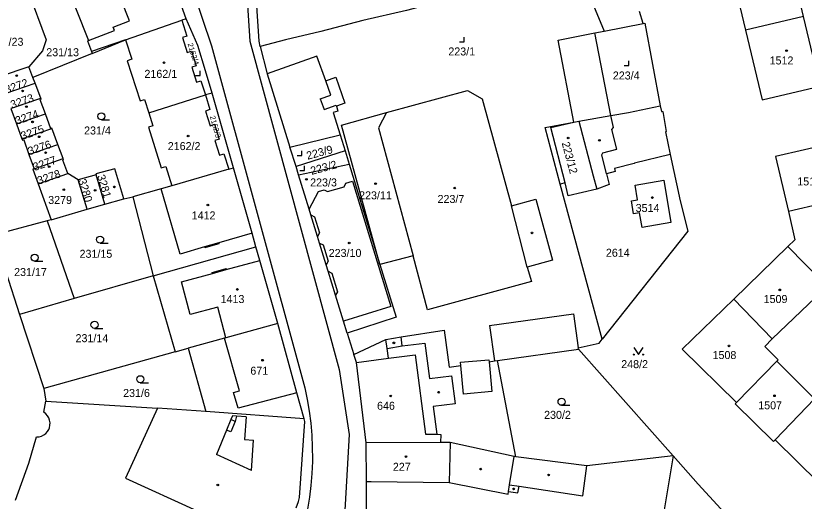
# Model space of a CAD drawing. Extents: x -679220 to -673243, y -1075091 to -1066557.
# Drawn here: x -676182 to -676014.5, y -1071736.7 to -1071633.5 of the extents above; entities that cross this region are included whole.
import ezdxf

# ---------------------------------------------------------------- set-up
doc = ezdxf.new("R2010")
doc.units = 0
for name, color, linetype in [('Hranice parcel', 7, 'Continuous'), ('Parcelní čísla', 7, 'Continuous'), ('Vnitřní kresba', 7, 'Continuous'), ('Značky budov', 7, 'Continuous'), ('Značky kultur', 7, 'Continuous')]:
    doc.layers.add(name, color=color, linetype=linetype)

msp = doc.modelspace()

# ---------------------------------------------------------------- linework, layer by layer
at = {"layer": 'Hranice parcel'}
for p, q in [((-676145.76, -1071634.12), (-676151.72, -1071617.55)), ((-676048.69, -1071635.13), (-676049.48, -1071632.57)), ((-676158.64, -1071638.61), (-676146.7, -1071634.45)), ((-676145.76, -1071634.12), (-676146.7, -1071634.45)), ((-676014.66, -1071633.66), (-676026.99, -1071636.54)), ((-676165.71, -1071641.49), (-676158.64, -1071638.61)), ((-676165.71, -1071641.49), (-676178.31, -1071646.61)), ((-676179.16, -1071644.33), (-676185.27, -1071646.43)), ((-676178.31, -1071646.61), (-676179.16, -1071644.33)), ((-676184, -1071649.93), (-676177.86, -1071647.82)), ((-676177.86, -1071647.82), (-676178.31, -1071646.61)), ((-676176.67, -1071651.01), (-676177.86, -1071647.82)), ((-676182.84, -1071653.13), (-676176.67, -1071651.01)), ((-676153.73, -1071654.12), (-676141.7, -1071650.33)), ((-676140.29, -1071649.98), (-676141.7, -1071650.33)), ((-676135.76, -1071665.81), (-676140.29, -1071649.98)), ((-676181.78, -1071656.49), (-676175.68, -1071654.37)), ((-676174.53, -1071657.5), (-676175.68, -1071654.37)), ((-676112.77, -1071656.77), (-676103.2, -1071654.04)), ((-676181.78, -1071656.49), (-676180.65, -1071659.66)), ((-676180.65, -1071659.66), (-676174.53, -1071657.5)), ((-676179.17, -1071662.97), (-676173.03, -1071660.83)), ((-676171.92, -1071663.86), (-676173.03, -1071660.83)), ((-676179.17, -1071662.97), (-676178.07, -1071666.01)), ((-676122.44, -1071665.53), (-676123.73, -1071661.42)), ((-676112.02, -1071662.17), (-676122.44, -1071665.53)), ((-676112.02, -1071662.17), (-676111.15, -1071665.03)), ((-676178.07, -1071666.01), (-676171.92, -1071663.86)), ((-676136.74, -1071666.1), (-676148.81, -1071669.62)), ((-676136.74, -1071666.1), (-676135.76, -1071665.81)), ((-676121.9, -1071667.28), (-676122.44, -1071665.53)), ((-676121.9, -1071667.28), (-676111.15, -1071665.03)), ((-676177.24, -1071669.21), (-676170.92, -1071667.01)), ((-676168.68, -1071668.36), (-676170.92, -1071667.01)), ((-676164.91, -1071667.31), (-676168.68, -1071668.36)), ((-676163.04, -1071673.55), (-676164.91, -1071667.31)), ((-676119.65, -1071674.63), (-676121.9, -1071667.28)), ((-676177.24, -1071669.21), (-676174.48, -1071676.86)), ((-676166.79, -1071674.64), (-676168.68, -1071668.36)), ((-676057.44, -1071702.25), (-676066.33, -1071669.3)), ((-676163.04, -1071673.55), (-676159.05, -1071672.4)), ((-676159.05, -1071672.4), (-676157.09, -1071671.95)), ((-676157.09, -1071671.95), (-676152.82, -1071688.75)), ((-676005.59, -1071672.24), (-676017.88, -1071675.12)), ((-676174.48, -1071676.86), (-676166.79, -1071674.64)), ((-676166.79, -1071674.64), (-676163.04, -1071673.55)), ((-676175.28, -1071677.08), (-676186.72, -1071680.18)), ((-676174.48, -1071676.86), (-676175.28, -1071677.08)), ((-676175.28, -1071677.08), (-676169.53, -1071693.6)), ((-676152.82, -1071688.75), (-676130.95, -1071682.6)), ((-676017.97, -1071682.56), (-676029.47, -1071693.75)), ((-676009.72, -1071691.04), (-676017.97, -1071682.56)), ((-676152.82, -1071688.75), (-676169.53, -1071693.6)), ((-676152.82, -1071688.75), (-676148.14, -1071704.96)), ((-676021.31, -1071702.14), (-676009.72, -1071691.04)), ((-676169.53, -1071693.6), (-676181.15, -1071696.97)), ((-676021.31, -1071702.14), (-676029.47, -1071693.75)), ((-676181.15, -1071696.97), (-676176.04, -1071712.7)), ((-676111.57, -1071700.93), (-676112.37, -1071698.39)), ((-676111.57, -1071700.93), (-676110.14, -1071705.5)), ((-676148.14, -1071704.96), (-676145.33, -1071704.18)), ((-676145.33, -1071704.18), (-676141.6, -1071717.61)), ((-676079.69, -1071706.8), (-676062.48, -1071704.34)), ((-676062.48, -1071704.34), (-676042.38, -1071727.03)), ((-676148.14, -1071704.96), (-676176.04, -1071712.7)), ((-676075.79, -1071727.22), (-676079.69, -1071706.8)), ((-676020.31, -1071706.89), (-676028.93, -1071715.7)), ((-676012.33, -1071714.92), (-676020.31, -1071706.89)), ((-676176.04, -1071712.7), (-676175.61, -1071715.39)), ((-676012.33, -1071714.92), (-676020.69, -1071723.63)), ((-676175.98, -1071717.78), (-676175.61, -1071715.39)), ((-676175.61, -1071715.39), (-676151.9, -1071716.94)), ((-676141.6, -1071717.61), (-676151.9, -1071716.94)), ((-676120.74, -1071719.2), (-676141.6, -1071717.61)), ((-676042.38, -1071727.03), (-676048.46, -1071763.85))]:
    msp.add_line(p, q, dxfattribs=at)
for points in [[(-676099.38, -1071590.43), (-676125.1, -1071603.36), (-676134.03, -1071611.63), (-676132.28, -1071638.9), (-676113.31, -1071708.7), (-676111.17, -1071722.51), (-676112.16, -1071739.84), (-676114.63, -1071749.43), (-676121.41, -1071764.03), (-676135.15, -1071783.33), (-676142.46, -1071792.76), (-676166.36, -1071822.04), (-676175.39, -1071833.12), (-676182.45, -1071844.4), (-676187.2, -1071855.01), (-676191.45, -1071871.27), (-676192.51, -1071884.43), (-676191.2, -1071899.37), (-676183.88, -1071917.06), (-676171.89, -1071936.65), (-676157.14, -1071950.29), (-676143.77, -1071959.8), (-676108.24, -1071982.64), (-676103.47, -1071979.82)], [(-676130.08, -1071640.05), (-676130.27, -1071638.92), (-676132.05, -1071612.1), (-676123.87, -1071605), (-676098.3, -1071593.66)], [(-676152.11, -1071615.93), (-676148.36, -1071616.28), (-676140.37, -1071639.9), (-676120.56, -1071712.56)], [(-676014.66, -1071633.66), (-676018.16, -1071618.83), (-676030.51, -1071621.69), (-676026.99, -1071636.54)], [(-676171.89, -1071625.11), (-676166.49, -1071638.73), (-676166.73, -1071638.83), (-676165.85, -1071641.12), (-676165.71, -1071641.49)], [(-676084.03, -1071625.87), (-676089.49, -1071628.58), (-676093.25, -1071630.57), (-676095.5, -1071631.44), (-676098.98, -1071632.38), (-676108.29, -1071634.5), (-676117.2, -1071636.81), (-676124.66, -1071638.59), (-676130.08, -1071640.05)], [(-676179.39, -1071628.06), (-676175.53, -1071638.64), (-676176.27, -1071640.96), (-676179.16, -1071644.33)], [(-676146.7, -1071634.45), (-676145.64, -1071637.82), (-676146.59, -1071638.12), (-676145.6, -1071641.29), (-676144.64, -1071640.99), (-676143.65, -1071644.15), (-676144.6, -1071644.45), (-676143.6, -1071647.63), (-676142.65, -1071647.33), (-676141.7, -1071650.33)], [(-676140.29, -1071649.98), (-676141.65, -1071645.22), (-676143.3, -1071639.79), (-676145.76, -1071634.12)], [(-676026.99, -1071636.54), (-676023.47, -1071651.39), (-676011.16, -1071648.49), (-676014.66, -1071633.66)], [(-676063.46, -1071656.11), (-676066.78, -1071638.69), (-676058.99, -1071637.15), (-676057.03, -1071636.77), (-676048.69, -1071635.13)], [(-676048.69, -1071635.13), (-676048.4, -1071635.08), (-676045.08, -1071652.62)], [(-676158.64, -1071638.61), (-676157.33, -1071642.74), (-676158.28, -1071643.05), (-676155.58, -1071651.59), (-676154.62, -1071651.29), (-676153.73, -1071654.12)], [(-676130.08, -1071640.05), (-676128.61, -1071645.86), (-676123.73, -1071661.42)], [(-676103.2, -1071654.04), (-676086.03, -1071649.36), (-676082.9, -1071651.16), (-676076.65, -1071673.87), (-676071.5, -1071672.48), (-676068, -1071685.48), (-676073.36, -1071686.93), (-676072.45, -1071689.95), (-676094.51, -1071696.03), (-676097.54, -1071684.49)], [(-676175.68, -1071654.37), (-676176.81, -1071651.34), (-676176.58, -1071651.24), (-676176.67, -1071651.01)], [(-676141.7, -1071650.33), (-676140.72, -1071653.44), (-676141.68, -1071653.74), (-676140.69, -1071656.87), (-676139.74, -1071656.57), (-676138.75, -1071659.7), (-676139.71, -1071660), (-676138.72, -1071663.13), (-676137.77, -1071662.83), (-676136.74, -1071666.1)], [(-676063.46, -1071656.11), (-676062.41, -1071655.91), (-676055.59, -1071654.72), (-676051.86, -1071654.04), (-676045.08, -1071652.62)], [(-676045.08, -1071652.62), (-676044.82, -1071653.87), (-676044.53, -1071653.83), (-676043.83, -1071658.08), (-676043.98, -1071658.14), (-676042.96, -1071662.97)], [(-676182.84, -1071653.13), (-676182.98, -1071653.18), (-676181.78, -1071656.49)], [(-676153.73, -1071654.12), (-676152.85, -1071656.88), (-676153.81, -1071657.18), (-676151.08, -1071665.8), (-676150.12, -1071665.5), (-676148.81, -1071669.62)], [(-676103.2, -1071654.04), (-676104.96, -1071657.29), (-676097.54, -1071684.49)], [(-676066.33, -1071669.3), (-676069.56, -1071657.27), (-676063.46, -1071656.11)], [(-676173.03, -1071660.83), (-676174.3, -1071657.41), (-676174.53, -1071657.5)], [(-676097.54, -1071684.49), (-676104.63, -1071686.35), (-676112.77, -1071656.77)], [(-676180.65, -1071659.66), (-676180.54, -1071659.95), (-676180.28, -1071659.86), (-676179.17, -1071662.97)], [(-676123.73, -1071661.42), (-676113.07, -1071658.83), (-676112.02, -1071662.17)], [(-676005.59, -1071672.24), (-676008.33, -1071660.56), (-676020.61, -1071663.44), (-676017.88, -1071675.12)], [(-676042.96, -1071662.97), (-676050.58, -1071664.81), (-676050.62, -1071664.92), (-676054.84, -1071665.97), (-676054.69, -1071666.58), (-676056.52, -1071667.09), (-676055.97, -1071669.37), (-676058.59, -1071670.33), (-676064.63, -1071671.74), (-676065.28, -1071668.98), (-676066.33, -1071669.3)], [(-676042.96, -1071662.97), (-676040.87, -1071672.83), (-676039.2, -1071679.27), (-676057.44, -1071702.25)], [(-676170.92, -1071667.01), (-676171.97, -1071664.2), (-676171.81, -1071664.14), (-676171.92, -1071663.86)], [(-676178.07, -1071666.01), (-676178.35, -1071666.11), (-676177.24, -1071669.21)], [(-676159.05, -1071672.4), (-676160.92, -1071666), (-676164.96, -1071667.12), (-676164.91, -1071667.31)], [(-676130.95, -1071682.6), (-676131.76, -1071679.71), (-676135.76, -1071665.81)], [(-676111.15, -1071665.03), (-676104.63, -1071686.35), (-676101.17, -1071697.56), (-676111.57, -1071700.93)], [(-676148.81, -1071669.62), (-676151.07, -1071670.28), (-676157.09, -1071671.95)], [(-676119.65, -1071674.63), (-676117.65, -1071670.88), (-676116.48, -1071670.53), (-676115.77, -1071670.87), (-676112.25, -1071669.86), (-676111.85, -1071669.11), (-676110.46, -1071668.68), (-676102.32, -1071695.32), (-676112.37, -1071698.39)], [(-676049.91, -1071672.61), (-676050.41, -1071669.47), (-676044.35, -1071668.46), (-676042.85, -1071677.47), (-676048.93, -1071678.5), (-676049.48, -1071675.36), (-676050.75, -1071675.59), (-676051.18, -1071672.82), (-676049.91, -1071672.61)], [(-676112.37, -1071698.39), (-676114.06, -1071692.92), (-676115.61, -1071687.82), (-676116.03, -1071686.43), (-676117.44, -1071681.82), (-676117.87, -1071680.43), (-676119.29, -1071675.81), (-676119.65, -1071674.63)], [(-676017.88, -1071675.12), (-676016.48, -1071681.1), (-676017.97, -1071682.56)], [(-676186.72, -1071680.18), (-676184.08, -1071687.93), (-676181.15, -1071696.97)], [(-676126.28, -1071698.88), (-676130.13, -1071685.49), (-676130.95, -1071682.6)], [(-676029.47, -1071693.75), (-676040.42, -1071704.4), (-676028.93, -1071715.7)], [(-676126.28, -1071698.88), (-676137.33, -1071701.97), (-676137.62, -1071702.05), (-676145.33, -1071704.18)], [(-676120.74, -1071719.2), (-676122.3, -1071713.65), (-676126.28, -1071698.88)], [(-676110.14, -1071705.5), (-676103.36, -1071702.29), (-676100.12, -1071701.77), (-676090.96, -1071700.35), (-676089.95, -1071708.22), (-676087.44, -1071707.87), (-676087.51, -1071707.12), (-676081.5, -1071706.6), (-676081.46, -1071707.04), (-676080.26, -1071706.88), (-676079.69, -1071706.8)], [(-676062.48, -1071704.34), (-676062.52, -1071704.09), (-676058.1, -1071703.08), (-676057.44, -1071702.25)], [(-676020.31, -1071706.89), (-676020.05, -1071706.63), (-676022.91, -1071703.78), (-676021.31, -1071702.14)], [(-676107.55, -1071724.3), (-676109.62, -1071707.17), (-676110.14, -1071705.5)], [(-676120.56, -1071712.56), (-676120.05, -1071715.06), (-676119.63, -1071717.58), (-676119.32, -1071720.11), (-676119.1, -1071722.65), (-676118.99, -1071725.2), (-676118.97, -1071727.75), (-676118.98, -1071728.23), (-676119.08, -1071730.78), (-676119.29, -1071733.32), (-676119.59, -1071735.86), (-676119.99, -1071738.38), (-676120.49, -1071740.88), (-676121.09, -1071743.36), (-676121.78, -1071745.81), (-676122.57, -1071748.24)], [(-676028.93, -1071715.7), (-676029.21, -1071715.98), (-676021.04, -1071723.99), (-676020.69, -1071723.63)], [(-676177.55, -1071723.03), (-676177.02, -1071722.98), (-676176.5, -1071722.84), (-676176.03, -1071722.6), (-676175.6, -1071722.28), (-676175.24, -1071721.88), (-676174.97, -1071721.42), (-676174.82, -1071721.06), (-676174.7, -1071720.54), (-676174.69, -1071720.01), (-676174.77, -1071719.48), (-676174.94, -1071718.98), (-676175.21, -1071718.52), (-676175.56, -1071718.11), (-676175.98, -1071717.78)], [(-676151.9, -1071716.94), (-676158.66, -1071731.81), (-676143.45, -1071738.76), (-676144.34, -1071741.61), (-676144.49, -1071741.53), (-676144.89, -1071742.57), (-676149.15, -1071752.96), (-676152.35, -1071759.83), (-676153.84, -1071762.37)], [(-676122.39, -1071738.06), (-676121.89, -1071736.77), (-676121.68, -1071735.9), (-676120.6, -1071719.71), (-676120.74, -1071719.2)], [(-676182.03, -1071736.5), (-676179.22, -1071728.58), (-676177.55, -1071723.03)], [(-676075.79, -1071727.22), (-676076.13, -1071727.18), (-676089.68, -1071724.22), (-676091.73, -1071724.19), (-676107.55, -1071724.3)], [(-676107.45, -1071740.64), (-676107.5, -1071732.52), (-676107.55, -1071724.3)], [(-676020.69, -1071723.63), (-676006.84, -1071737.31), (-676004.84, -1071735.27)], [(-676042.38, -1071727.03), (-676060.72, -1071729.17), (-676075.79, -1071727.22)], [(-676029.38, -1071778.12), (-676014.53, -1071757.61), (-676037.01, -1071733.09), (-676042.38, -1071727.03)]]:
    msp.add_lwpolyline(points, dxfattribs=at)
at = {"layer": 'Vnitřní kresba'}
for p, q in [((-676063.04, -1071622.13), (-676057.03, -1071636.77)), ((-676157.81, -1071634.59), (-676159.55, -1071630.04)), ((-676161.3, -1071635.93), (-676157.81, -1071634.59)), ((-676161.02, -1071636.64), (-676161.3, -1071635.93)), ((-676166.49, -1071638.73), (-676161.02, -1071636.64)), ((-676055.59, -1071654.72), (-676058.99, -1071637.15)), ((-676158.64, -1071638.61), (-676165.85, -1071641.12)), ((-676118.02, -1071642.07), (-676128.61, -1071645.86)), ((-676116.13, -1071647.34), (-676118.02, -1071642.07)), ((-676116.13, -1071647.34), (-676113.96, -1071646.58)), ((-676115.05, -1071650.36), (-676116.13, -1071647.34)), ((-676113.96, -1071646.58), (-676112.05, -1071652.06)), ((-676117.31, -1071651.17), (-676115.05, -1071650.36)), ((-676117.31, -1071651.17), (-676116.5, -1071653.43)), ((-676116.5, -1071653.43), (-676113.91, -1071652.5)), ((-676113.91, -1071652.5), (-676113.86, -1071652.69)), ((-676112.05, -1071652.06), (-676113.86, -1071652.69)), ((-676113.86, -1071652.69), (-676113.6, -1071653.76)), ((-676113.6, -1071653.76), (-676114.54, -1071654.08)), ((-676114.54, -1071654.08), (-676113.07, -1071658.83)), ((-676068.31, -1071657.26), (-676063.46, -1071656.11)), ((-676062.41, -1071655.91), (-676059.35, -1071667.49)), ((-676055.04, -1071657.23), (-676055.59, -1071654.72)), ((-676065.28, -1071668.98), (-676068.31, -1071657.26)), ((-676055.36, -1071657.67), (-676055.04, -1071657.23)), ((-676054.29, -1071661.85), (-676055.36, -1071657.67)), ((-676057.53, -1071663.02), (-676057.26, -1071662.62)), ((-676056.52, -1071667.09), (-676057.53, -1071663.02)), ((-676057.26, -1071662.62), (-676054.29, -1071661.85)), ((-676059.35, -1071667.49), (-676058.59, -1071670.33)), ((-676147.05, -1071684.14), (-676151.07, -1071670.28)), ((-676073.36, -1071686.93), (-676076.65, -1071673.87)), ((-676119.29, -1071675.81), (-676118.54, -1071676.2)), ((-676118.54, -1071676.2), (-676117.47, -1071679.67)), ((-676131.76, -1071679.71), (-676138.87, -1071681.77)), ((-676117.47, -1071679.67), (-676117.87, -1071680.43)), ((-676141.85, -1071682.64), (-676147.05, -1071684.14)), ((-676138.87, -1071681.77), (-676141.85, -1071682.64)), ((-676141.78, -1071682.86), (-676141.85, -1071682.64)), ((-676138.81, -1071682), (-676141.78, -1071682.86)), ((-676138.87, -1071681.77), (-676138.81, -1071682)), ((-676117.44, -1071681.82), (-676116.69, -1071682.22)), ((-676116.69, -1071682.22), (-676115.64, -1071685.69)), ((-676137.25, -1071687.44), (-676130.13, -1071685.49)), ((-676115.64, -1071685.69), (-676116.03, -1071686.43)), ((-676140.24, -1071688.04), (-676137.31, -1071687.23)), ((-676140.18, -1071688.25), (-676140.24, -1071688.04)), ((-676140.18, -1071688.25), (-676137.25, -1071687.44)), ((-676137.31, -1071687.23), (-676137.25, -1071687.44)), ((-676115.61, -1071687.82), (-676114.86, -1071688.22)), ((-676146.79, -1071690.08), (-676140.18, -1071688.25)), ((-676114.86, -1071688.22), (-676113.65, -1071692.17)), ((-676144.95, -1071696.98), (-676146.79, -1071690.08)), ((-676113.65, -1071692.17), (-676114.06, -1071692.92)), ((-676139.08, -1071695.41), (-676144.95, -1071696.98)), ((-676137.33, -1071701.97), (-676139.08, -1071695.41)), ((-676081.34, -1071699.31), (-676063.53, -1071696.83)), ((-676063.53, -1071696.83), (-676062.52, -1071704.09)), ((-676081.34, -1071699.31), (-676080.26, -1071706.88)), ((-676134.47, -1071713.22), (-676137.62, -1071702.05)), ((-676103.09, -1071704.19), (-676103.36, -1071702.29)), ((-676099.87, -1071703.69), (-676100.12, -1071701.77)), ((-676099.87, -1071703.69), (-676095.08, -1071703.07)), ((-676095.08, -1071703.07), (-676094.09, -1071710.63)), ((-676103.09, -1071704.19), (-676099.87, -1071703.69)), ((-676102.78, -1071706.29), (-676103.09, -1071704.19)), ((-676109.62, -1071707.17), (-676102.78, -1071706.29)), ((-676102.78, -1071706.29), (-676097.15, -1071705.56)), ((-676097.15, -1071705.56), (-676094.92, -1071722.44)), ((-676086.9, -1071713.93), (-676087.44, -1071707.87)), ((-676081.46, -1071707.04), (-676080.89, -1071713.39)), ((-676094.09, -1071710.63), (-676089.44, -1071710.02)), ((-676089.44, -1071710.02), (-676088.66, -1071715.97)), ((-676135.72, -1071713.58), (-676134.47, -1071713.22)), ((-676134.71, -1071716.89), (-676135.72, -1071713.58)), ((-676122.3, -1071713.65), (-676134.71, -1071716.89)), ((-676080.89, -1071713.39), (-676086.9, -1071713.93)), ((-676088.66, -1071715.97), (-676093.29, -1071716.58)), ((-676093.29, -1071716.58), (-676092.51, -1071722.47)), ((-676136.29, -1071719.33), (-676137.2, -1071721.55)), ((-676135.96, -1071718.54), (-676136.29, -1071719.33)), ((-676135.36, -1071719.71), (-676136.29, -1071719.33)), ((-676135.36, -1071719.71), (-676136.28, -1071721.93)), ((-676135.12, -1071718.61), (-676135.96, -1071718.54)), ((-676135.12, -1071718.61), (-676135.36, -1071719.71)), ((-676133.07, -1071718.76), (-676135.12, -1071718.61)), ((-676133.07, -1071718.76), (-676133.39, -1071723.55)), ((-676137.2, -1071721.55), (-676139.36, -1071726.77)), ((-676136.28, -1071721.93), (-676137.2, -1071721.55)), ((-676094.92, -1071722.44), (-676092.51, -1071722.47)), ((-676092.51, -1071722.47), (-676091.71, -1071722.48)), ((-676091.71, -1071722.48), (-676091.73, -1071724.19)), ((-676133.39, -1071723.55), (-676131.5, -1071723.68)), ((-676131.93, -1071730.16), (-676131.5, -1071723.68)), ((-676089.68, -1071724.22), (-676089.95, -1071732.72)), ((-676131.93, -1071730.16), (-676139.36, -1071726.77)), ((-676077.1, -1071733.19), (-676076.13, -1071727.18)), ((-676061.52, -1071735.51), (-676060.72, -1071729.17)), ((-676107.5, -1071732.52), (-676106.51, -1071732.53)), ((-676106.51, -1071732.53), (-676089.95, -1071732.72)), ((-676089.95, -1071732.72), (-676077.42, -1071735.17)), ((-676077.33, -1071734.59), (-676077.1, -1071733.19)), ((-676077.1, -1071733.19), (-676075.08, -1071733.49)), ((-676077.42, -1071735.17), (-676077.33, -1071734.59)), ((-676077.33, -1071734.59), (-676075.31, -1071734.92)), ((-676075.31, -1071734.92), (-676075.08, -1071733.49)), ((-676075.08, -1071733.49), (-676061.52, -1071735.51))]:
    msp.add_line(p, q, dxfattribs=at)
at = {"layer": 'Značky budov'}
for centre in [(-676018.27, -1071640.91), (-676150.48, -1071643.48), (-676181.77, -1071646.21), (-676180.51, -1071649.47), (-676179.7, -1071652.83), (-676178.4, -1071656.05), (-676176.98, -1071659.22), (-676145.36, -1071659.06), (-676064.65, -1071659.47), (-676058.01, -1071659.99), (-676175.63, -1071662.6), (-676174.87, -1071665.56), (-676161.02, -1071669.87), (-676120.23, -1071668.26), (-676105.56, -1071669.19), (-676171.76, -1071670.47), (-676165.11, -1071670.6), (-676088.74, -1071670.11), (-676046.77, -1071672.14), (-676141.16, -1071673.72), (-676072.33, -1071679.64), (-676111.15, -1071681.79), (-676134.9, -1071691.68), (-676019.71, -1071691.76), (-676101.66, -1071703.03), (-676030.48, -1071703.66), (-676129.56, -1071706.72), (-676102.33, -1071714.31), (-676092.15, -1071713.52), (-676020.83, -1071714.27), (-676099.08, -1071727.2), (-676083.22, -1071729.86), (-676068.8, -1071731.1), (-676139.06, -1071733.24), (-676076.23, -1071734.06)]:
    msp.add_circle(centre, 0.175, dxfattribs=at)
at = {"layer": 'Značky kultur'}
for p, q in [((-676087.72, -1071639.01), (-676086.72, -1071639.01)), ((-676086.72, -1071639.01), (-676086.72, -1071638.01)), ((-676052.79, -1071644.06), (-676051.79, -1071644.06)), ((-676051.79, -1071644.06), (-676051.79, -1071643.06)), ((-676143.78, -1071646.2), (-676142.78, -1071646.2)), ((-676142.78, -1071646.2), (-676142.78, -1071645.2)), ((-676163.78, -1071655.62), (-676162.03, -1071655.62)), ((-676121.21, -1071663.18), (-676121.21, -1071662.18)), ((-676122.21, -1071663.18), (-676121.21, -1071663.18)), ((-676121.62, -1071666.36), (-676120.62, -1071666.36)), ((-676120.62, -1071666.36), (-676120.62, -1071665.36)), ((-676164.06, -1071681.83), (-676162.31, -1071681.83)), ((-676177.96, -1071685.66), (-676176.21, -1071685.66)), ((-676165.24, -1071699.94), (-676163.49, -1071699.94)), ((-676155.52, -1071711.5), (-676153.77, -1071711.5)), ((-676066.05, -1071716.3), (-676064.3, -1071716.3))]:
    msp.add_line(p, q, dxfattribs=at)
msp.add_lwpolyline([(-676050.73, -1071704.01), (-676049.73, -1071705.51), (-676048.73, -1071704.01)], dxfattribs=at)
for centre, radius in [((-676163.78, -1071654.87), 0.75), ((-676164.06, -1071681.08), 0.75), ((-676177.96, -1071684.91), 0.75), ((-676165.24, -1071699.19), 0.75), ((-676050.73, -1071705.51), 0.1), ((-676048.73, -1071705.51), 0.1), ((-676155.52, -1071710.75), 0.75), ((-676066.05, -1071715.55), 0.75)]:
    msp.add_circle(centre, radius, dxfattribs=at)

# ---------------------------------------------------------------- texts
at = {"layer": 'Parcelní čísla'}
for s, p in [('231/23', (-676187.29, -1071639.87)), ('231/13', (-676175.49, -1071642.09)), ('223/1', (-676090.1, -1071641.93)), ('1512', (-676021.87, -1071643.84)), ('2162/1', (-676154.64, -1071646.69)), ('223/4', (-676055.17, -1071647.04)), ('231/4', (-676167.46, -1071658.73)), ('2162/2', (-676149.69, -1071662.05)), ('223/3', (-676119.45, -1071669.77)), ('1511', (-676016, -1071669.56)), ('223/11', (-676109.05, -1071672.52)), ('3279', (-676175.08, -1071673.5)), ('223/7', (-676092.39, -1071673.29)), ('3514', (-676050.32, -1071675.2)), ('1412', (-676144.61, -1071676.78)), ('223/10', (-676115.51, -1071684.76)), ('2614', (-676056.64, -1071684.72)), ('231/15', (-676168.42, -1071684.94)), ('231/17', (-676182.32, -1071688.82)), ('1413', (-676138.47, -1071694.56)), ('1509', (-676023.14, -1071694.56)), ('231/14', (-676169.27, -1071702.88)), ('1508', (-676033.99, -1071706.47)), ('671', (-676132.15, -1071709.8)), ('248/2', (-676053.38, -1071708.4)), ('231/6', (-676159.17, -1071714.53)), ('646', (-676105.24, -1071717.25)), ('1507', (-676024.29, -1071717.15)), ('230/2', (-676069.76, -1071719.18)), ('227', (-676101.88, -1071730.22))]:
    msp.add_text(s, height=1.7, dxfattribs=at).set_placement(p)
for s, height, rotation, p in [('2162/4', 1.14, 287, (-676145.49, -1071639.47)), ('3272', 1.7, 19, (-676183.95, -1071650.06)), ('3273', 1.7, 19, (-676182.76, -1071653.27)), ('3274', 1.7, 19, (-676181.72, -1071656.67)), ('2162/3', 1.14, 286, (-676140.77, -1071654.91)), ('3275', 1.7, 19, (-676180.56, -1071659.9)), ('3276', 1.7, 19, (-676179.04, -1071663.15)), ('223/9', 1.7, 15, (-676119.99, -1071664.11)), ('223/12', 1.7, 285, (-676066.04, -1071660.54)), ('3277', 1.7, 19, (-676177.97, -1071666.5)), ('223/2', 1.7, 15, (-676119.12, -1071667.32)), ('3278', 1.7, 19, (-676177.06, -1071669.4)), ('3281', 1.7, 287, (-676164.72, -1071667.55)), ('3280', 1.7, 287, (-676168.72, -1071668.45))]:
    msp.add_text(s, height=height, rotation=rotation, dxfattribs=at).set_placement(p)

doc.saveas('drawing.dxf')
